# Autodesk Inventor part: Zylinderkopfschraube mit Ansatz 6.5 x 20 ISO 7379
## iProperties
Shininess: 64.0
Length Units: 11269
Angle Units: 11279
Time Units: 11290
Mass Units: 11283
Length Display Precision: 3
Angle Display Precision: 2
Compacted: True
Part Number: Zylinderkopfschraube mit Ansatz 6.5 x 20 ISO 7379
Document SubType Name: Modeling
Created: 2003-09
Material: Standard
Designer: Robert Hüttner
Manufacturer: Standard
Standards Organization: Custom
Density: 0.0
Volumn: 0.0
Area: 0.0
PropertySet Name: Model Information
Control State: 0
Master: False
Checked Out: False
Bezeichnung: Zylinderkopfschraube mit Ansatz
Größe: 6.5 x 20
Norm: ISO 7379
Author: Robert Hüttner
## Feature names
1. Basis1
